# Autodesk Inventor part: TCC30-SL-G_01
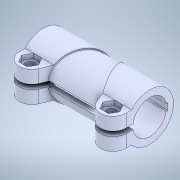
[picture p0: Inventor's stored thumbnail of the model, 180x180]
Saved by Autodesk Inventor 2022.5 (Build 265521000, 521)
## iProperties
Created: 2023-09
Part Number: TCC30-SL-G_01
Material: 一般
Document SubType Name: Modeling
Designer: ImaoCorp
Density: 1 g/cm^3
Appearance: 既定
Author: ImaoCorp
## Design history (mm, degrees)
feature "TCC30-SL-G_01"
node "ソリッド1"
